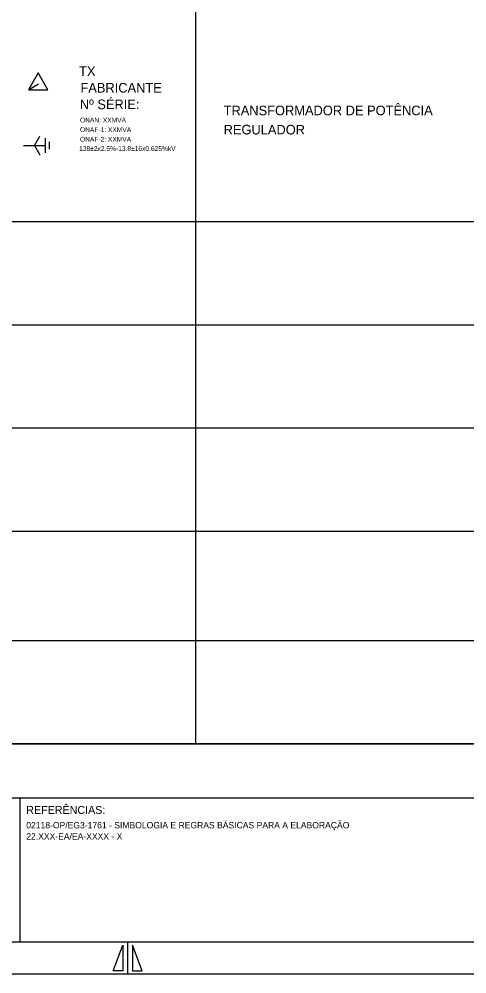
# Model space of a CAD drawing. Extents: x 563 to 3226, y 358 to 960.
# Drawn here: x 999.7 to 1139.5, y 358 to 656.2 of the extents above; entities that cross this region are included whole.
import ezdxf

# ---------------------------------------------------------------- set-up
doc = ezdxf.new("R2010")
doc.units = 0
doc.layers.add('Default', color=7, linetype='Continuous')
doc.layers.add('New Level (0)', color=7, linetype='Continuous')

msp = doc.modelspace()

# ---------------------------------------------------------------- linework, layer by layer
at = {"layer": 'Default'}
for p, q in [((1005.63, 639.36), (1002.6, 634.12)), ((1008.65, 634.12), (1005.63, 639.36)), ((1002.6, 634.12), (1005.69, 635.99)), ((1002.6, 634.12), (1008.65, 634.12)), ((1004.5, 616.7), (1006.19, 619.64)), ((1007.89, 614.44), (1007.89, 618.97)), ((1009.02, 617.84), (1009.02, 615.57)), ((1001.1, 616.7), (1007.89, 616.7)), ((1004.5, 616.7), (1006.19, 613.77)), ((1010.15, 616.7), (1010.15, 616.7))]:
    msp.add_line(p, q, dxfattribs=at)
at = {"layer": 'New Level (0)'}
for p, q in [((1054.73, 721.84), (1054.73, 429.83)), ((603.14, 592.93), (1303.31, 592.93)), ((603.14, 560.7), (1303.31, 560.7)), ((603.14, 528.47), (1303.31, 528.47)), ((603.14, 528.47), (1303.31, 528.47)), ((603.14, 496.25), (1303.31, 496.25)), ((603.14, 462.06), (1303.31, 462.06)), ((603.14, 429.83), (1303.31, 429.83)), ((572.58, 412.96), (1393.58, 412.96)), ((999.91, 412.96), (999.91, 367.96)), ((572.58, 367.96), (1393.58, 367.96)), ((572.58, 367.96), (1393.58, 367.96)), ((1029.08, 358.96), (1032.08, 366.96)), ((1032.08, 366.96), (1032.08, 358.96)), ((1033.58, 367.96), (1033.58, 357.96)), ((1035.08, 366.96), (1035.08, 358.96)), ((1038.08, 358.96), (1035.08, 366.96)), ((562.58, 357.96), (1403.58, 357.96)), ((562.58, 357.96), (1403.58, 357.96)), ((1032.08, 358.96), (1029.08, 358.96)), ((1035.08, 358.96), (1038.08, 358.96))]:
    msp.add_line(p, q, dxfattribs=at)
msp.add_lwpolyline([(953.22, 915.21), (1157.18, 915.21), (1157.18, 429.83), (953.22, 429.83)], close=True, dxfattribs=at)

# ---------------------------------------------------------------- texts
at = {"layer": 'Default'}
for s, height, p in [('TX', 3, (1018.41, 638.39)), ('FABRICANTE', 3, (1018.84, 633.22)), ('Nº SÉRIE: ', 3, (1018.64, 628.04)), ('TRANSFORMADOR DE POTÊNCIA', 3, (1063.56, 626.14)), ('ONAN: XXMVA', 1.5, (1018.69, 623.89)), ('ONAF-1: XXMVA', 1.5, (1018.69, 620.89)), ('REGULADOR', 3, (1063.56, 620.14)), ('ONAF-2: XXMVA', 1.5, (1018.69, 617.89)), ('138±2x2.5%-13.8±16x0.625%kV', 1.5, (1018.43, 614.99))]:
    msp.add_text(s, height=height, dxfattribs=at).set_placement(p)
at = {"layer": 'New Level (0)'}
for s, height, p in [('REFERÊNCIAS:', 2.5, (1001.91, 407.91)), ('02118-OP/EG3-1761 - SIMBOLOGIA E REGRAS BÁSICAS PARA A ELABORAÇÃO', 2, (1001.91, 403.41)), ('22.XXX-EA/EA-XXXX - X', 2, (1001.91, 399.91))]:
    msp.add_text(s, height=height, dxfattribs=at).set_placement(p)

doc.saveas('drawing.dxf')
